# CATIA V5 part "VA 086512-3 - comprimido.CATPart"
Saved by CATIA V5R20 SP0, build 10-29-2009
Part number: VA 086512-3 - comprimido
Revision: ANY
Definition: UNKNOWN
Nomenclature: VA 086512-3 - comprimido
Source: Unknown
Bounding box of the stored display mesh (mm): x -2.45 to 2.45, y 0 to 4.849, z -2.45 to 2.45
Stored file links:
  C:\Users\Utente\Desktop\IO LAVORO\3D X SITO CF\CUMSA\3D files VA\VA 086512\VA 086512-3 - comprimido.CATPart
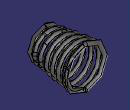
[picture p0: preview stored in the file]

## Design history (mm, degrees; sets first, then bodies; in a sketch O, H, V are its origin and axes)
Body1 "Cortar-Extruir2" (main body)
  Solid1: solid without history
